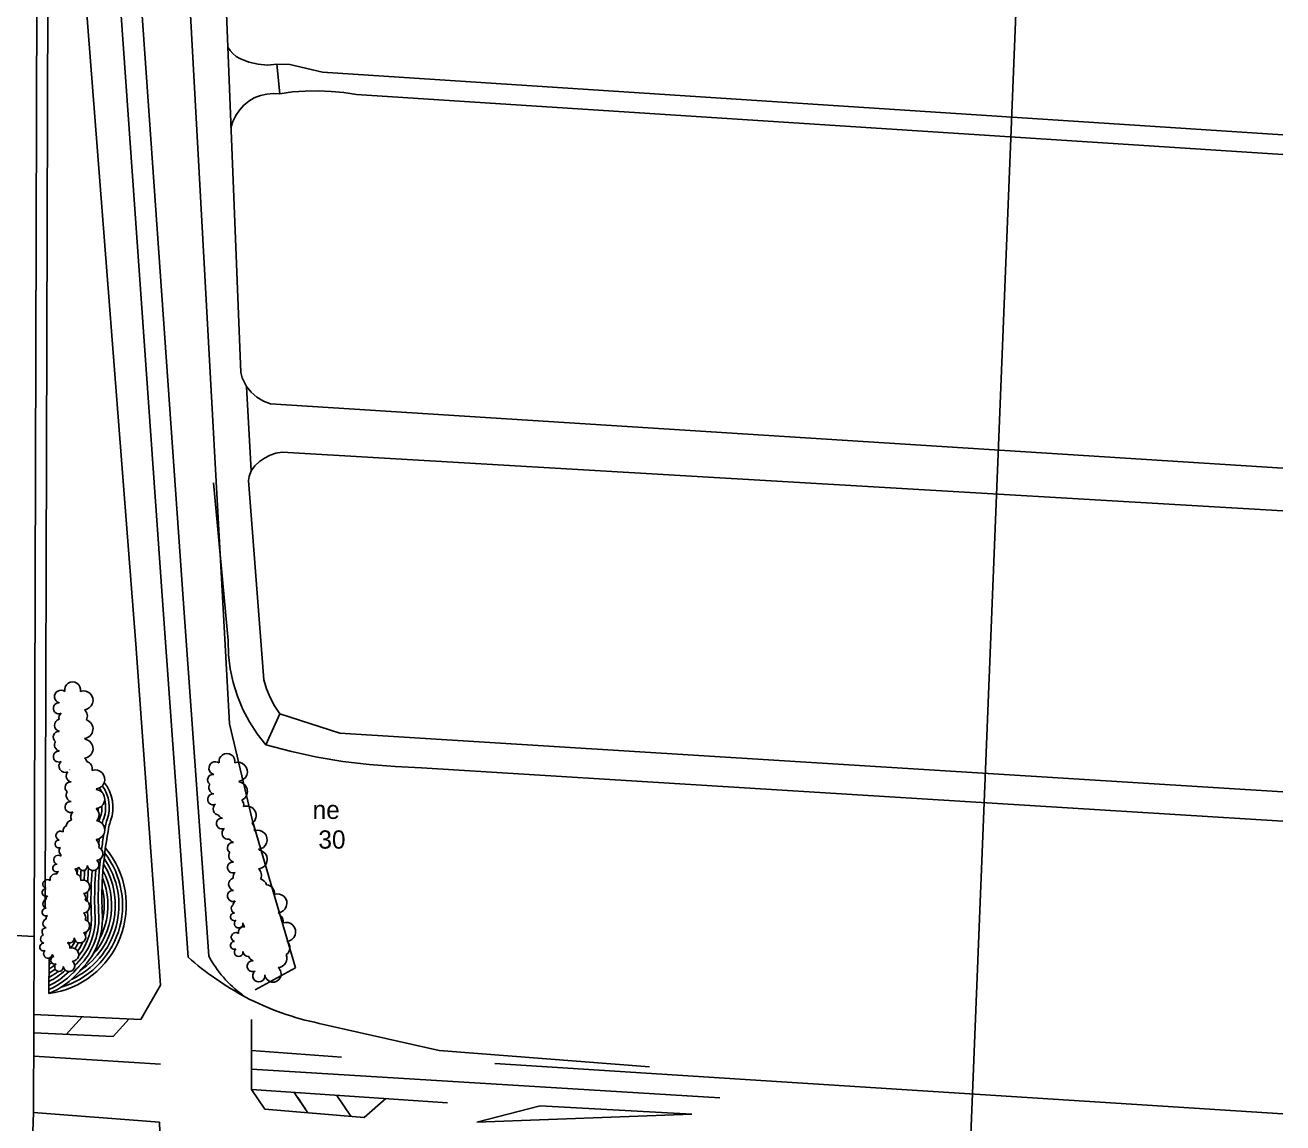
# Model space of a CAD drawing. Extents: x -9648 to 41057, y -12373 to 40276.
# Drawn here: x 8857 to 9546, y 12090 to 12692 of the extents above; entities that cross this region are included whole.
import ezdxf

# ---------------------------------------------------------------- set-up
doc = ezdxf.new("R2010")
doc.units = 0
for name, color, linetype in [('RD_P_GR_Lt', 7, 'Continuous'), ('RD_P_Noise_Wall', 7, 'Continuous'), ('SC_Scratch1', 7, 'Continuous'), ('SH_Data', 7, 'Continuous')]:
    doc.layers.add(name, color=color, linetype=linetype)

msp = doc.modelspace()

# ---------------------------------------------------------------- linework, layer by layer
at = {"layer": 'RD_P_GR_Lt'}
msp.add_line((8869.51, 12820.52), (8867.78, 12208.03), dxfattribs=at)
at = {"layer": 'RD_P_Noise_Wall'}
msp.add_line((8928.31, 13047.86), (8968.82, 12308.76), dxfattribs=at)
at = {"layer": 'SC_Scratch1'}
msp.add_line((9419.02, 13174.65), (9328.38, 10916.47), dxfattribs=at)
at = {"layer": 'SH_Data'}
for p, q in [((8884.89, 13044.79), (8932.71, 12368.86)), ((8896.22, 13045.59), (8944.04, 12369.66)), ((8864.13, 13037.71), (8861.73, 12192.24)), ((8864.13, 13037.71), (8917.55, 12352.55)), ((8961.93, 12828.99), (8975.03, 12501.53)), ((8969.13, 12678.01), (8967.93, 12679.91)), ((8970.73, 12676.31), (8969.13, 12678.01)), ((8972.53, 12674.81), (8970.73, 12676.31)), ((8974.53, 12673.61), (8972.53, 12674.81)), ((8979.43, 12671.71), (8974.53, 12673.61)), ((8984.53, 12670.51), (8979.43, 12671.71)), ((8989.73, 12670.01), (8984.53, 12670.51)), ((8994.83, 12670.51), (8989.73, 12670.01)), ((8996.33, 12654.21), (8994.83, 12670.51)), ((8994.83, 12670.51), (9001.83, 12670.41)), ((9001.83, 12670.41), (9019.83, 12666.21)), ((9019.83, 12666.21), (9021.73, 12666.01)), ((9019.83, 12666.21), (9546.27, 12631.82)), ((8979.43, 12650.21), (8982.43, 12652.01)), ((8982.43, 12652.01), (8985.83, 12653.31)), ((8985.83, 12653.31), (8989.33, 12654.11)), ((8989.33, 12654.11), (8992.83, 12654.41)), ((8992.83, 12654.41), (8996.33, 12654.21)), ((8996.33, 12654.21), (9003.33, 12655.31)), ((9003.33, 12655.31), (9010.33, 12655.81)), ((9010.33, 12655.81), (9017.43, 12655.91)), ((9017.43, 12655.91), (9024.53, 12655.61)), ((9024.53, 12655.61), (9031.53, 12654.91)), ((9031.53, 12654.91), (9038.53, 12653.81)), ((9038.53, 12653.81), (9546.27, 12621.02)), ((8972.23, 12642.41), (8974.23, 12645.31)), ((8974.23, 12645.31), (8976.63, 12648.01)), ((8976.63, 12648.01), (8979.43, 12650.21)), ((8969.63, 12635.71), (8970.73, 12639.11)), ((8970.73, 12639.11), (8972.23, 12642.41)), ((8975.03, 12501.53), (8975.83, 12498.53)), ((8975.83, 12498.53), (8978.13, 12493.83)), ((8980.73, 12490.63), (8978.13, 12493.83)), ((8978.13, 12493.83), (8980.73, 12447.54)), ((8983.83, 12487.93), (8980.73, 12490.63)), ((8987.43, 12485.73), (8983.83, 12487.93)), ((8991.23, 12484.33), (8987.43, 12485.73)), ((9546.27, 12448.94), (8991.23, 12484.33)), ((8982.73, 12450.24), (8985.23, 12452.64)), ((8985.23, 12452.64), (8988.03, 12454.54)), ((8988.03, 12454.54), (8991.03, 12456.14)), ((8991.03, 12456.14), (8994.23, 12457.24)), ((8994.23, 12457.24), (8997.63, 12457.84)), ((8997.63, 12457.84), (9546.27, 12425.54)), ((8980.73, 12447.54), (8979.63, 12444.54)), ((8980.73, 12447.54), (8982.73, 12450.24)), ((8968.13, 12354.55), (8960.03, 12441.04)), ((8979.63, 12444.54), (8979.23, 12442.34)), ((8979.23, 12442.34), (8987.63, 12333.05)), ((8944.04, 12369.66), (8957.41, 12181.62)), ((8932.71, 12368.86), (8932.71, 12368.85)), ((8932.71, 12368.85), (8946.08, 12180.81)), ((8917.55, 12352.55), (8930.94, 12165.46)), ((8968.33, 12346.75), (8968.13, 12354.55)), ((8969.23, 12339.05), (8968.33, 12346.75)), ((8970.83, 12331.45), (8969.23, 12339.05)), ((8973.13, 12323.95), (8970.83, 12331.45)), ((8987.63, 12333.05), (8989.13, 12328.05)), ((8989.13, 12328.05), (8991.13, 12323.25)), ((8976.13, 12316.75), (8973.13, 12323.95)), ((8991.13, 12323.25), (8993.53, 12318.75)), ((8979.73, 12309.85), (8976.13, 12316.75)), ((8996.33, 12314.35), (8988.73, 12297.25)), ((8993.53, 12318.75), (8996.33, 12314.35)), ((8996.33, 12314.35), (9029.23, 12303.65)), ((8981.49, 12255.64), (8968.82, 12308.76)), ((8983.93, 12303.35), (8979.73, 12309.85)), ((8988.73, 12297.25), (8983.93, 12303.35)), ((9029.23, 12303.65), (9546.27, 12271.56)), ((8988.73, 12297.25), (9002.73, 12293.65)), ((9002.73, 12293.65), (9016.83, 12290.65)), ((9016.83, 12290.65), (9031.03, 12288.26)), ((9031.03, 12288.26), (9045.32, 12286.46)), ((9045.32, 12286.46), (9059.62, 12285.36)), ((9059.62, 12285.36), (9074.02, 12284.76)), ((9074.02, 12284.76), (9546.27, 12255.46)), ((9005.02, 12175.02), (8981.49, 12255.64)), ((8746.95, 12198.8), (8861.73, 12192.24)), ((8861.73, 12192.24), (8861.46, 12095.64)), ((8870, 12180.42), (8869.84, 12160.96)), ((8982.83, 12162.98), (9005.02, 12175.02)), ((8930.94, 12165.46), (8920.17, 12146.74)), ((8920.17, 12146.74), (8861.61, 12149.51)), ((8879.29, 12138.57), (8888.1, 12148.26)), ((8905.09, 12137.35), (8913.89, 12147.04)), ((8980.97, 12146.72), (8980.97, 12108.26)), ((9018.03, 12144.6), (9083.78, 12129.73)), ((8905.09, 12137.35), (8861.58, 12139.4)), ((8980.97, 12129.66), (9030.14, 12126.15)), ((9083.78, 12129.73), (9199.1, 12120.78)), ((8861.54, 12126.7), (8931.06, 12122.22)), ((9114.32, 12122.67), (9546.27, 12094.98)), ((9114.32, 12122.67), (9546.27, 12094.98)), ((8980.97, 12119.4), (9237.54, 12103.79)), ((8980.97, 12108.26), (9088.25, 12101.11)), ((8988.12, 12097.53), (8980.97, 12108.26)), ((9011.76, 12095.59), (9004.36, 12106.7)), ((9011.76, 12095.59), (9006.21, 12103.93)), ((9035.41, 12093.66), (9027.75, 12105.14)), ((9054.53, 12103.36), (9042.65, 12093.06)), ((8861.46, 12095.64), (8859.74, 12048.38)), ((8861.46, 12095.64), (8930.37, 12090.47)), ((9042.65, 12093.06), (8988.12, 12097.53)), ((9104.34, 12090.38), (9139.2, 12099.32)), ((9104.34, 12090.38), (9222.34, 12094.85)), ((9139.2, 12099.32), (9222.34, 12094.85)), ((8930.37, 12090.47), (8931.23, 12069.5))]:
    msp.add_line(p, q, dxfattribs=at)
for centre, radius, start, end in [((8882.8, 12327.46), 4.36, 349.14531, 191.45961), ((8876.45, 12323.74), 3.53, 53.82996, 255.0376), ((8888.81, 12321.74), 5.2, 274.94757, 109.45715), ((8875.22, 12317.35), 3, 84.0047, 295.97412), ((8878.64, 12312.05), 3.35, 129.06254, 191.39014), ((8886.41, 12313.09), 4.49, 332.01663, 50.57371), ((8876.45, 12308.03), 3.53, 107.87759, 255.0376), ((8888.81, 12306.03), 5.2, 274.94757, 72.5073), ((8875.22, 12301.64), 3, 84.0047, 234.5634), ((8886.41, 12297.38), 4.49, 41.83102, 50.57371), ((8888.81, 12295.27), 5.2, 274.94757, 79.55213), ((8875.22, 12290.87), 3, 84.0047, 295.97412), ((8876.45, 12297.27), 3.53, 146.96719, 255.0376), ((8878.64, 12285.58), 3.35, 129.06254, 296.02749), ((8886.41, 12286.62), 4.49, 20.60599, 50.57371), ((8889.22, 12284.07), 4.36, 349.14531, 71.31216), ((8961.07, 12284.55), 3.53, 53.82996, 255.0376), ((8967.42, 12288.27), 4.36, 349.14531, 191.45961), ((8973.43, 12282.55), 5.2, 274.94757, 109.45715), ((8882.86, 12280.35), 3.53, 141.07938, 255.0376), ((8878.64, 12285.58), 3.35, 321.77203, 321.77204), ((8895.23, 12278.35), 5.2, 274.94757, 109.45715), ((8959.84, 12278.16), 3, 84.0047, 234.5634), ((8881.64, 12273.96), 3, 84.0047, 234.5634), ((8892.82, 12269.7), 4.49, 41.83102, 50.57371), ((8895.23, 12267.59), 5.2, 274.94757, 79.55213), ((8883.06, 12263.09), 17.87, 26.85379, 36.27774), ((8883.06, 12263.09), 19.87, 340.05768, 36.31143), ((8883.06, 12263.09), 21.87, 340.05768, 38.55996), ((8961.07, 12273.79), 3.53, 146.96719, 255.0376), ((8971.03, 12273.9), 4.49, 41.83102, 50.57371), ((8973.43, 12271.79), 5.2, 294.46073, 79.55213), ((8881.64, 12263.2), 3, 84.0047, 295.97412), ((8882.86, 12269.59), 3.53, 146.96719, 255.0376), ((8883.06, 12263.09), 17.87, 340.05768, 13.74007), ((8959.84, 12267.4), 3, 84.0047, 295.97412), ((8972.24, 12264.27), 4.36, 349.14531, 39.73923), ((8885.06, 12257.9), 3.35, 129.06254, 212.70765), ((8892.82, 12258.94), 4.49, 314.80993, 50.57371), ((8883.06, 12263.09), 13.87, 351.6036, 358.2899), ((8883.06, 12263.09), 15.87, 340.05768, 2.99658), ((8963.26, 12262.1), 3.35, 129.06254, 262.36419), ((8965.88, 12260.55), 3.53, 210.00487, 255.0376), ((8978.25, 12258.55), 5.2, 303.78638, 109.45715), ((8880.66, 12250.14), 3.08, 115.43561, 191.45961), ((8882.86, 12252.61), 3.53, 100.10597, 175.06469), ((8895.23, 12250.61), 5.2, 274.94757, 81.57796), ((8923.36, 12248.47), 27, 160.05768, 165.13598), ((9103.98, 12212.82), 205.1, 168.83675, 181.23415), ((8923.36, 12248.47), 25, 160.05768, 166.82055), ((9103.98, 12212.82), 207.1, 168.83675, 169.39395), ((8923.36, 12248.47), 23, 160.05768, 168.83675), ((8923.36, 12248.47), 21, 160.05768, 168.83675), ((8964.65, 12254.16), 3, 84.0047, 295.97412), ((8978.25, 12250.97), 4.36, 349.14531, 48.52458), ((8875.3, 12242.98), 2.12, 84.0047, 295.97412), ((8876.17, 12247.51), 2.5, 53.82996, 255.0376), ((8892.82, 12241.96), 4.49, 348.01271, 50.57371), ((9103.98, 12212.82), 209.1, 170.88616, 171.61778), ((9103.98, 12212.82), 207.1, 170.08529, 172.48647), ((8968.08, 12248.87), 3.35, 129.06254, 282.01083), ((8971.89, 12247.25), 3.53, 207.93994, 255.0376), ((8984.26, 12245.25), 5.2, 274.94757, 109.45715), ((8863.38, 12209.36), 48.82, 277.60596, 39.9947), ((8877.72, 12239.24), 2.37, 129.06254, 236.1292), ((8895.74, 12237.67), 3.67, 274.94757, 66.29902), ((8970.67, 12240.85), 3, 84.0047, 234.5634), ((8971.89, 12236.49), 3.53, 146.96719, 255.0376), ((8981.86, 12236.6), 4.49, 41.83102, 50.57371), ((8984.26, 12234.48), 5.2, 274.94757, 79.55213), ((8874.1, 12229.75), 2.12, 84.0047, 295.97412), ((8874.97, 12234.27), 2.5, 53.82996, 255.0376), ((8879.46, 12236.9), 3.08, 172.94396, 191.45961), ((8863.38, 12209.36), 46.82, 286.22621, 37.70398), ((8863.38, 12209.36), 44.82, 294.70895, 35.02305), ((8888.55, 12230.82), 2.37, 194.94166, 9.54124), ((8863.38, 12209.36), 42.82, 303.3543, 31.81882), ((8894.04, 12231.55), 3.18, 186.17219, 50.57371), ((9103.98, 12212.82), 207.1, 173.90744, 181.2204), ((8970.67, 12230.09), 3, 84.0047, 295.97412), ((8873.51, 12223.53), 3.08, 76.85739, 191.45961), ((8876.52, 12226), 2.37, 129.06254, 167.2743), ((8883.71, 12232.85), 3.67, 274.94757, 313.96376), ((8882.01, 12226.74), 3.18, 355.17698, 50.57371), ((8884.27, 12223.53), 3.08, 349.14531, 72.95729), ((9103.98, 12212.82), 219.1, 175.59395, 176.43966), ((9103.98, 12212.82), 217.1, 175.80195, 176.91402), ((9103.98, 12212.82), 215.1, 175.78522, 177.26029), ((9103.98, 12212.82), 213.1, 175.48598, 177.49994), ((9103.98, 12212.82), 211.1, 175.76048, 181.19514), ((8863.38, 12209.36), 40.82, 317.80656, 27.86305), ((9103.98, 12212.82), 209.1, 175.63976, 181.20743), ((8863.38, 12209.36), 38.82, 331.94483, 22.68986), ((8974.09, 12224.8), 3.35, 129.06254, 190.27697), ((8981.86, 12225.84), 4.49, 332.85354, 50.57371), ((8868.15, 12216.37), 2.12, 84.0047, 295.97412), ((8869.01, 12220.9), 2.5, 53.82996, 255.0376), ((8888.52, 12219.48), 3.67, 274.94757, 109.45715), ((8863.38, 12209.36), 36.82, 346.4422, 14.91019), ((8970.67, 12214.45), 3, 84.0047, 295.97412), ((8971.89, 12220.84), 3.53, 108.08591, 255.0376), ((8984.26, 12218.84), 5.2, 18.54827, 72.15601), ((8989.08, 12216.14), 4.36, 349.14531, 88.53975), ((8869.01, 12210.13), 2.5, 108.9116, 255.0376), ((8870.57, 12212.63), 2.37, 129.06254, 183.25413), ((8886.82, 12213.37), 3.18, 337.9919, 50.57371), ((8888.52, 12208.72), 3.67, 274.94757, 70.20516), ((9103.98, 12212.82), 215.1, 179.2008, 179.21511), ((9103.98, 12212.82), 213.1, 178.96114, 180.34625), ((8974.09, 12209.15), 3.35, 129.06254, 173.85154), ((8995.09, 12210.42), 5.2, 274.94757, 109.45715), ((8868.15, 12205.61), 2.12, 84.0047, 295.97412), ((8870.57, 12201.87), 2.37, 129.06254, 183.25413), ((8860.38, 12201.98), 34.82, 314.77879, 5.57855), ((8860.38, 12201.98), 32.82, 321.64728, 5.57855), ((8860.38, 12201.98), 36.82, 314.77879, 5.57855), ((8860.38, 12201.98), 38.82, 314.77879, 5.57855), ((8886.82, 12202.6), 3.18, 337.9919, 50.57371), ((8919.92, 12207.79), 29, 183.58979, 185.57855), ((8860.38, 12201.98), 30.82, 357.26994, 5.57855), ((8919.92, 12207.79), 27, 178.66904, 185.57855), ((8919.92, 12207.79), 25, 178.56969, 185.57855), ((8919.92, 12207.79), 23, 178.4571, 185.57855), ((8919.92, 12207.79), 21, 178.32816, 185.57855), ((8971.42, 12203.01), 2.12, 84.0047, 295.97412), ((8972.29, 12207.53), 2.5, 127.57619, 255.0376), ((8992.68, 12201.77), 4.49, 27.6738, 50.57371), ((8993.89, 12200.49), 4.36, 349.14531, 50.4905), ((8868.15, 12194.85), 2.12, 84.0047, 229.22603), ((8869.01, 12199.37), 2.5, 108.9116, 255.0376), ((8888.52, 12197.96), 3.67, 274.94757, 70.20516), ((8973.84, 12199.27), 2.37, 129.06254, 9.54124), ((8976.78, 12194.52), 3.08, 80.16047, 191.45961), ((8979.33, 12200), 3.18, 186.17219, 230.42697), ((8999.9, 12194.77), 5.2, 274.94757, 109.45715), ((8867.75, 12190.95), 2.5, 113.1721, 255.0376), ((8881.33, 12191.11), 2.37, 239.73286, 9.54124), ((8860.38, 12201.98), 26.82, 323.25048, 333.20443), ((8886.82, 12191.84), 3.18, 186.17219, 50.57371), ((8860.38, 12201.98), 30.82, 342.82681, 346.45981), ((8972.29, 12191.89), 2.5, 53.82996, 255.0376), ((8866.88, 12186.43), 2.12, 84.0047, 295.97412), ((8869.3, 12182.68), 2.37, 129.06254, 352.95732), ((8876.49, 12189.53), 3.67, 348.93944, 352.67207), ((8878.26, 12186.36), 3.08, 349.14531, 53.28576), ((8860.38, 12201.98), 24.82, 325.6746, 327.77115), ((8882.51, 12182.31), 3.67, 274.94757, 109.45715), ((8860.38, 12201.98), 28.82, 325.42027, 332.73311), ((8860.38, 12201.98), 30.82, 324.95625, 335.22548), ((8971.42, 12187.37), 2.12, 84.0047, 295.97412), ((8973.84, 12183.62), 2.37, 129.06254, 9.54124), ((8979.33, 12184.36), 3.18, 186.17219, 270.87383), ((8997.5, 12186.12), 4.49, 302.18868, 50.57371), ((8852.91, 12201.7), 32.12, 302.0485, 310.47146), ((8852.91, 12201.7), 30.12, 304.5074, 307.58822), ((8872.9, 12179.21), 2.12, 102.25935, 295.97412), ((8873.76, 12183.73), 2.5, 212.26566, 223.2532), ((8874.79, 12183.42), 3.18, 206.19921, 222.38046), ((8875.32, 12175.46), 2.37, 129.06254, 9.54124), ((8880.81, 12176.2), 3.18, 186.17219, 50.57371), ((8902.51, 12159.51), 27, 134.77879, 135.80503), ((8860.38, 12201.98), 32.82, 314.77879, 315.10188), ((8902.51, 12159.51), 25, 134.77879, 137.8371), ((9062.31, 12314.99), 177.51, 229.09986, 241.51875), ((9013.61, 12211.44), 63.61, 207.95654, 233.66285), ((8981.5, 12175.94), 3, 84.0047, 295.97412), ((8982.72, 12182.33), 3.53, 199.01169, 255.0376), ((8995.09, 12180.33), 5.2, 274.94757, 22.53582), ((8852.91, 12201.7), 44.12, 292.57252, 319.61983), ((8852.91, 12201.7), 42.12, 293.73425, 319.61983), ((8852.91, 12201.7), 40.12, 295.02416, 314.37146), ((8852.91, 12201.7), 38.12, 296.46575, 312.79541), ((8852.91, 12201.7), 36.12, 298.08894, 307.68677), ((8852.91, 12201.7), 34.12, 299.93262, 306.5971), ((8902.51, 12159.51), 23, 134.77879, 139.61983), ((8902.51, 12159.51), 21, 134.77879, 139.61983), ((8984.92, 12170.65), 3.35, 129.06254, 9.54124), ((8992.68, 12171.68), 4.49, 186.17219, 50.57371), ((9013.61, 12211.44), 63.61, 233.92516, 235.59234), ((9049.1, 12295.91), 154.46, 242.44987, 258.39567)]:
    msp.add_arc(centre, radius, start, end, dxfattribs=at)

# ---------------------------------------------------------------- texts
at = {"layer": 'SC_Scratch1'}
for s, p in [('ne', (9014.39, 12256.7)), ('30', (9017.55, 12240.41))]:
    msp.add_text(s, height=10, dxfattribs=at).set_placement(p)

doc.saveas('drawing.dxf')
